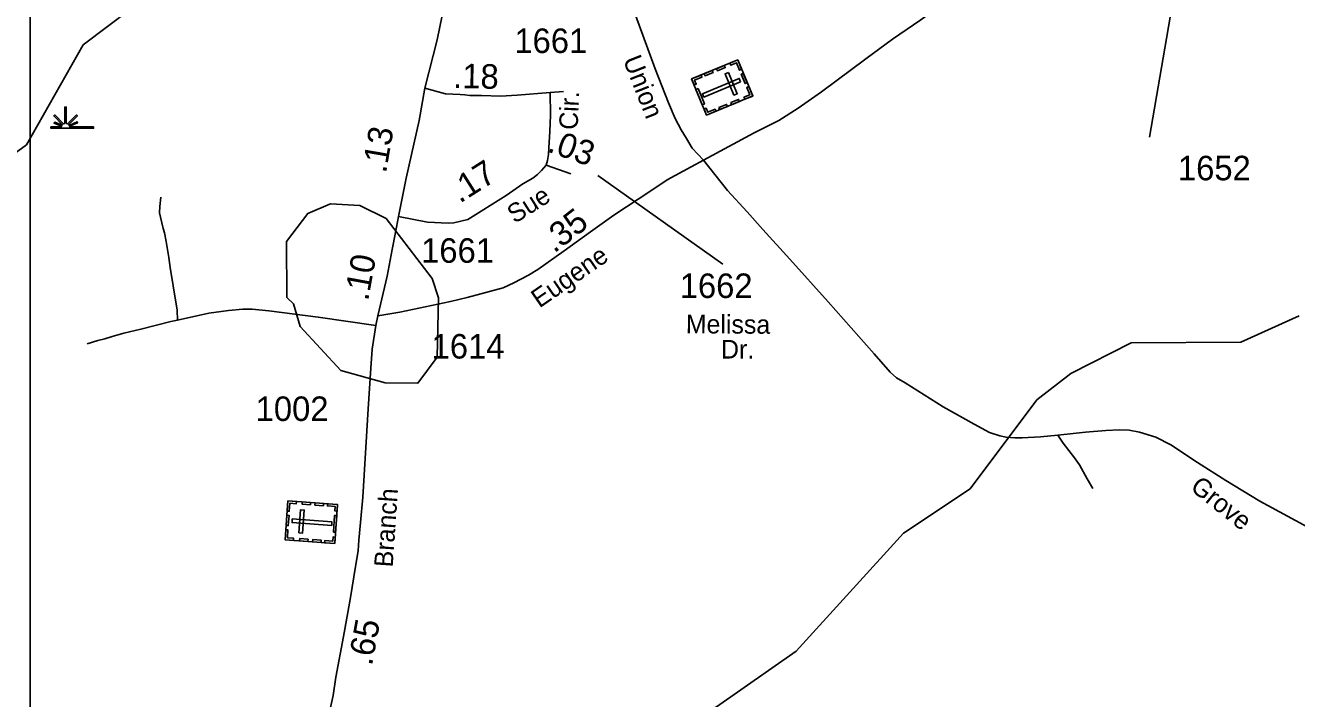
# Model space of a CAD drawing. Extents: x 2093524 to 2270757, y 289120 to 570408.
# Drawn here: x 2122806 to 2129291, y 538299 to 541732 of the extents above; entities that cross this region are included whole.
import ezdxf

# ---------------------------------------------------------------- set-up
doc = ezdxf.new("R2010")
doc.units = 0
for name, color, linetype in [('Exist Cultural Cemetery CELL', 7, 'Continuous'), ('Exist Hydrographic Creek Single Shore', 7, 'Continuous'), ('Exist Hydrographic Pond Under 1500 Sq Ft', 7, 'Continuous'), ('Exist Hydrographic Swamp CELL', 7, 'Continuous'), ('Exist Road Non-System Type 51', 7, 'Continuous'), ('Exist Road Secondary Mileage Hundredths English Label', 7, 'Continuous'), ('Exist Road Secondary Type 51 Attributed', 7, 'Continuous'), ('Exist Road Secondary Type 51 Label', 7, 'Continuous'), ('Exist Road Secondary Type 51 Number Label', 7, 'Continuous'), ('Map Preparation Inset Cut Line', 7, 'Continuous')]:
    doc.layers.add(name, color=color, linetype=linetype)

msp = doc.modelspace()

# ---------------------------------------------------------------- linework, layer by layer
at = {"layer": 'Exist Cultural Cemetery CELL'}
for points in [[(2126440.1, 541555.8), (2126516.2, 541371.9), (2126280.9, 541274.6), (2126204.8, 541458.6)], [(2126331.6, 541511), (2126371.6, 541527.5), (2126376, 541517), (2126335.9, 541500.5)], [(2126400.1, 541539.3), (2126404.4, 541528.8), (2126434.2, 541541.1), (2126449.7, 541503.6), (2126460, 541507.9), (2126440.1, 541555.8)], [(2126217.5, 541428), (2126228.1, 541432.4), (2126219.7, 541452.7), (2126257.1, 541468.2), (2126252.8, 541478.5), (2126204.9, 541458.6)], [(2126454.7, 541443.9), (2126447.6, 541461.2), (2126260.2, 541383.7), (2126267.3, 541366.4)], [(2126269.5, 541485.3), (2126309.5, 541501.9), (2126313.8, 541491.4), (2126273.8, 541474.8)], [(2126392.8, 541492.1), (2126375.6, 541485), (2126420.6, 541376.2), (2126437.8, 541383.3)], [(2126468.4, 541487.4), (2126488.2, 541439.5), (2126477.7, 541435.1), (2126457.9, 541483)], [(2126237.4, 541409.9), (2126269.8, 541331.4), (2126259.3, 541327.1), (2126226.9, 541405.5)], [(2126476.2, 541355.2), (2126471.8, 541365.7), (2126501.6, 541378), (2126486.1, 541415.5), (2126496.4, 541419.8), (2126516.2, 541371.8)], [(2126343.3, 541312.7), (2126383.4, 541329.3), (2126387.7, 541318.7), (2126347.7, 541302.2)], [(2126404.3, 541337.9), (2126444.3, 541354.4), (2126448.6, 541343.9), (2126408.6, 541327.3)], [(2126268.2, 541305.2), (2126278.8, 541309.6), (2126287.3, 541289.3), (2126324.6, 541304.7), (2126328.9, 541294.4), (2126280.9, 541274.6)], [(2124130.3, 539108.6), (2124144.9, 539307.1), (2124398.8, 539288.5), (2124384.3, 539089.9)], [(2124188.1, 539304), (2124187.3, 539292.7), (2124155.2, 539295.1), (2124152.3, 539254.6), (2124141.2, 539255.4), (2124144.9, 539307.2)], [(2124201.2, 539144.3), (2124219.8, 539142.9), (2124228.4, 539260.3), (2124209.8, 539261.7)], [(2124260.2, 539287.3), (2124217, 539290.5), (2124217.8, 539301.8), (2124261, 539298.6)], [(2124325.9, 539282.4), (2124282.7, 539285.6), (2124283.6, 539297), (2124326.8, 539293.8)], [(2124396.4, 539255.4), (2124385, 539256.3), (2124386.6, 539278.2), (2124346.3, 539281.2), (2124347.1, 539292.3), (2124398.8, 539288.5)], [(2124135.8, 539182.4), (2124139.6, 539234.1), (2124150.9, 539233.3), (2124147.1, 539181.6)], [(2124167.5, 539215.1), (2124166.2, 539196.5), (2124368.4, 539181.7), (2124369.8, 539200.3)], [(2124377, 539148.1), (2124383.2, 539232.7), (2124394.6, 539231.9), (2124388.4, 539147.2)], [(2124173.5, 539105.4), (2124174.4, 539116.7), (2124142.3, 539119.1), (2124145.2, 539159.5), (2124134.1, 539160.3), (2124130.3, 539108.6)], [(2124247.5, 539099.9), (2124204.3, 539103.1), (2124205.1, 539114.5), (2124248.3, 539111.3)], [(2124386.7, 539122.9), (2124375.2, 539123.8), (2124373.6, 539101.8), (2124333.3, 539104.8), (2124332.5, 539093.7), (2124384.2, 539089.9)], [(2124314.5, 539095), (2124271.3, 539098.2), (2124272.2, 539109.5), (2124315.4, 539106.4)]]:
    msp.add_lwpolyline(points, close=True, dxfattribs=at)
at = {"layer": 'Exist Hydrographic Creek Single Shore'}
for points in [[(2122512.8, 540905.8), (2122811.7, 541122.9), (2123100.9, 541632.1), (2123465.9, 541910.1), (2124023.8, 542128.5), (2124281.8, 542188.9), (2124389.8, 542272.1), (2124513.9, 542413.9), (2124617.8, 542661.9), (2124686.2, 542775.3), (2124839.3, 542942.8), (2124961.7, 543041.8), (2124997.8, 543101.3), (2125023, 543166.1), (2125068, 543220.1), (2125104.5, 543314.5)], [(2125431.9, 538193.1), (2125773.9, 538045.1), (2125998.9, 538096.4), (2126330.8, 538257.1), (2126737.9, 538540.8), (2127285, 539143.2), (2127626, 539369.3), (2127965.9, 539821.7), (2128140, 539956), (2128448, 540113.9), (2129006, 540115.7), (2129304.9, 540250.7)]]:
    msp.add_lwpolyline(points, dxfattribs=at)
at = {"layer": 'Exist Hydrographic Pond Under 1500 Sq Ft'}
msp.add_lwpolyline([(2124640.8, 539908.3), (2124415.9, 539971.9), (2124206.9, 540195.9), (2124172.9, 540311.4), (2124138.8, 540344.9), (2124137.8, 540630.3), (2124245.9, 540772.5), (2124362.8, 540822.6), (2124511.8, 540813), (2124645.7, 540748), (2124880.9, 540441.5), (2124913.9, 540342.4), (2124906.8, 540040.8), (2124807.9, 539908.2), (2124640.8, 539908.3)], dxfattribs=at)
at = {"layer": 'Exist Hydrographic Swamp CELL'}
msp.add_lwpolyline([(2122936, 541214.6), (2122988.6, 541214.7), (2122990.6, 541218.3), (2122952.4, 541233.1), (2122955.3, 541238.3), (2122993, 541222.5), (2122994.6, 541225.4), (2122950.2, 541270), (2122955.3, 541275.1), (2123000.6, 541229.6), (2123006.9, 541232), (2123006.9, 541315.1), (2123014.2, 541315.1), (2123014.1, 541232), (2123020.5, 541229.6), (2123065.8, 541275.1), (2123070.9, 541270), (2123026.5, 541225.4), (2123028.5, 541221.8), (2123069.4, 541240.4), (2123071.8, 541235.4), (2123030.8, 541217.6), (2123032.4, 541214.7), (2123153.5, 541214.6), (2123153.5, 541207.5), (2122936, 541207.5)], close=True, dxfattribs=at)
at = {"layer": 'Exist Road Non-System Type 51'}
msp.add_line((2125550.8, 541395.1), (2125482.8, 541390.5), dxfattribs=at)
for points in [[(2123581.6, 540228.9), (2123580.6, 540278.9), (2123559.1, 540403.3), (2123545, 540497.6), (2123538, 540547.7), (2123523.7, 540630), (2123514.6, 540674.2), (2123509, 540696.3), (2123494.2, 540754.6), (2123490.7, 540776.7), (2123491.3, 540808.6), (2123496.3, 540856.5)], [(2124593.5, 540201), (2124299.9, 540244.4), (2124048.5, 540275.5), (2123962.7, 540285.2), (2123914.7, 540284.2), (2123842.6, 540277.6), (2123804.5, 540272.4), (2123742.3, 540263.7), (2123581.6, 540228.9)], [(2123581.6, 540228.9), (2123547.5, 540221.6), (2123394.7, 540182.7), (2123308.3, 540162.4), (2123248, 540145.6), (2123211.8, 540134.3), (2123175.6, 540125.1), (2123121.2, 540108.2)], [(2128251.8, 539371.1), (2128222.8, 539419.6), (2128184.2, 539490.4), (2128158.9, 539526.9), (2128100.5, 539602.1), (2128073.3, 539642.6)]]:
    msp.add_lwpolyline(points, dxfattribs=at)
at = {"layer": 'Exist Road Secondary Type 51 Attributed'}
msp.add_line((2125463.2, 541018.9), (2125588.3, 540974.4), dxfattribs=at)
for points in [[(2126264.6, 541044.7), (2126207.9, 541105), (2126178.2, 541154.6), (2126151.2, 541198.7), (2126121.5, 541256.3), (2126086.4, 541336.4), (2126018.8, 541510.2), (2125918, 541783.9), (2125728.9, 542263.9), (2125654.2, 542474.6), (2125565, 542704.2), (2125473.2, 542941.9), (2125436.3, 543040.9)], [(2124843.8, 541412.1), (2124905.9, 541658.8), (2124958.1, 541908.2), (2124975.3, 541995.5), (2125002.3, 542087.4), (2125027.5, 542176.5), (2125071.6, 542302.6), (2125158, 542523.2), (2125220.2, 542678.1), (2125251.7, 542777.1), (2125262.5, 542827.5), (2125267.9, 542872.5), (2125267.5, 542954.4), (2125265.8, 542991.3)], [(2126264.6, 541044.7), (2126524, 541183.4), (2126649.7, 541247.1), (2126748.9, 541309.1), (2126866.6, 541392.7), (2127094, 541562.1), (2127230, 541661.3), (2127374, 541760.4), (2127530.2, 541875.3), (2127731.3, 542027.2), (2127885.3, 542130.1), (2128019.2, 542221.4), (2128132.8, 542305.1), (2128265.1, 542418.4), (2128399.4, 542535.7), (2128509.4, 542633.5), (2128605.2, 542721.6), (2128649.9, 542758.7), (2128700.4, 542785.6), (2128748.9, 542806.7), (2128785.2, 542821.9), (2128837.4, 542832.9)], [(2128837.4, 542832.9), (2128792.9, 542607.8), (2128725.2, 542229.2), (2128540.6, 541161.5)], [(2124708.7, 540756.6), (2124748.1, 540953.3), (2124814.1, 541246.4), (2124843.8, 541412.1)], [(2125463.2, 541018.9), (2125469.7, 541042.8), (2125474.3, 541072.7), (2125477, 541106.7), (2125480.7, 541190.6), (2125484.4, 541274.5), (2125482.8, 541390.5), (2125314.5, 541375.9), (2125230.3, 541371.6), (2125132.4, 541373.6), (2125072.4, 541374.8), (2125048.5, 541377.2), (2125024.5, 541379.7), (2124949.1, 541382.4), (2124843.8, 541412.1)], [(2124603.4, 540250.5), (2124716.2, 540270.1), (2124975.3, 540324.4), (2125059, 540345.1), (2125242.8, 540393.5), (2125297.2, 540418.4), (2125372, 540458.9), (2125420.7, 540487.9), (2125555.1, 540581.9), (2125689.3, 540680), (2125808.1, 540763.8), (2125996.3, 540888.9), (2126080.1, 540944.8), (2126203, 541010.1), (2126264.6, 541044.7)], [(2124708.7, 540756.6), (2124857.3, 540727.8), (2124963.3, 540723), (2124991.4, 540724.5), (2125062.6, 540742.2), (2125258.9, 540863.7), (2125343.3, 540923.4), (2125393.9, 540952.4), (2125418.3, 540971.9), (2125438.7, 540991.4), (2125463.2, 541018.9)], [(2129385.3, 539152.3), (2129104.4, 539305.9), (2128930.5, 539411.4), (2128786.4, 539502.3), (2128650.2, 539593), (2128573, 539632.6), (2128489.6, 539658.3), (2128437.7, 539667.3), (2128387.8, 539670.3), (2128317.7, 539665.7), (2128213.6, 539657.8), (2128073.3, 539642.6), (2127985.1, 539634.4), (2127891, 539628.3), (2127853, 539629.1), (2127809.1, 539631.9), (2127777.2, 539638.6), (2127723.6, 539655.7), (2127646.5, 539699.2), (2127488.2, 539786.4), (2127294.7, 539908.3), (2127249.2, 539935.2), (2127217.8, 539963.8), (2127135.7, 540057.4), (2126901.1, 540322.1), (2126705.5, 540540), (2126568.5, 540690.8), (2126488.3, 540780.4), (2126388.6, 540890.4), (2126264.6, 541044.7)], [(2124603.4, 540250.5), (2124652, 540453.3), (2124676.8, 540588.8), (2124694.5, 540676.5), (2124708.7, 540756.6)], [(2124436.2, 536888.1), (2124362.1, 537271.5), (2124323.5, 537448.3), (2124304, 537564.7), (2124293.8, 537656.9), (2124289.3, 537733), (2124293.5, 537842.9), (2124303.7, 537948.6), (2124328.5, 538090.1), (2124344.1, 538167.8), (2124375.1, 538315.2), (2124388.9, 538408.9), (2124428.7, 538616.3), (2124462.9, 538804.5), (2124490.8, 538982.8), (2124503.4, 539053), (2124506.1, 539107), (2124516, 539196.2), (2124527.7, 539326.7), (2124554.8, 539776), (2124567.4, 539984), (2124574.6, 540080.4), (2124593.5, 540201), (2124603.4, 540250.5)]]:
    msp.add_lwpolyline(points, dxfattribs=at)
at = {"layer": 'Exist Road Secondary Type 51 Number Label'}
msp.add_line((2125725.7, 540966.5), (2126363.9, 540513.5), dxfattribs=at)
at = {"layer": 'Map Preparation Inset Cut Line'}
msp.add_lwpolyline([(2141792.3, 534352.7), (2122830.6, 534352.7), (2122830.6, 549698.5), (2141792.3, 549698.5)], close=True, dxfattribs=at)

# ---------------------------------------------------------------- texts
at = {"layer": 'Exist Road Secondary Mileage Hundredths English Label'}
for s, rotation, p in [('.18', 358.8289, (2124987.1, 541412.9)), ('.13', 80.23718, (2124645.4, 540975)), ('.03', 340.41798, (2125463.3, 541090)), ('.17', 32.31877, (2125021.7, 540822.3)), ('.35', 37.89819, (2125503.5, 540567.3)), ('.10', 79.62839, (2124553.8, 540323.3)), ('.65', 79.64255, (2124573.8, 538463))]:
    msp.add_text(s, height=125, rotation=rotation, dxfattribs=at).set_placement(p)
at = {"layer": 'Exist Road Secondary Type 51 Label'}
for s, rotation, p in [('Union', 291.5059, (2125853.2, 541556.7)), ('Cir.', 87.47437, (2125622.9, 541197.9)), ('Sue', 32.31877, (2125302.1, 540718.8)), ('Eugene', 34.66921, (2125428.3, 540288)), ('Melissa', 359.59954, (2126174.8, 540162.1)), ('Dr.', 359.95356, (2126354.7, 540033.2)), ('Grove', 321.28234, (2128743.4, 539367)), ('Branch', 86.07196, (2124679.3, 538966.4))]:
    msp.add_text(s, height=95, rotation=rotation, dxfattribs=at).set_placement(p)
at = {"layer": 'Exist Road Secondary Type 51 Number Label'}
for s, p in [('1661', (2125300.3, 541591.1)), ('1652', (2128685.7, 540942)), ('1661', (2124824.5, 540521.4)), ('1662', (2126143.9, 540341.7)), ('1614', (2124878.1, 540033)), ('1002', (2123980.5, 539714.6))]:
    msp.add_text(s, height=125, dxfattribs=at).set_placement(p)

doc.saveas('drawing.dxf')
